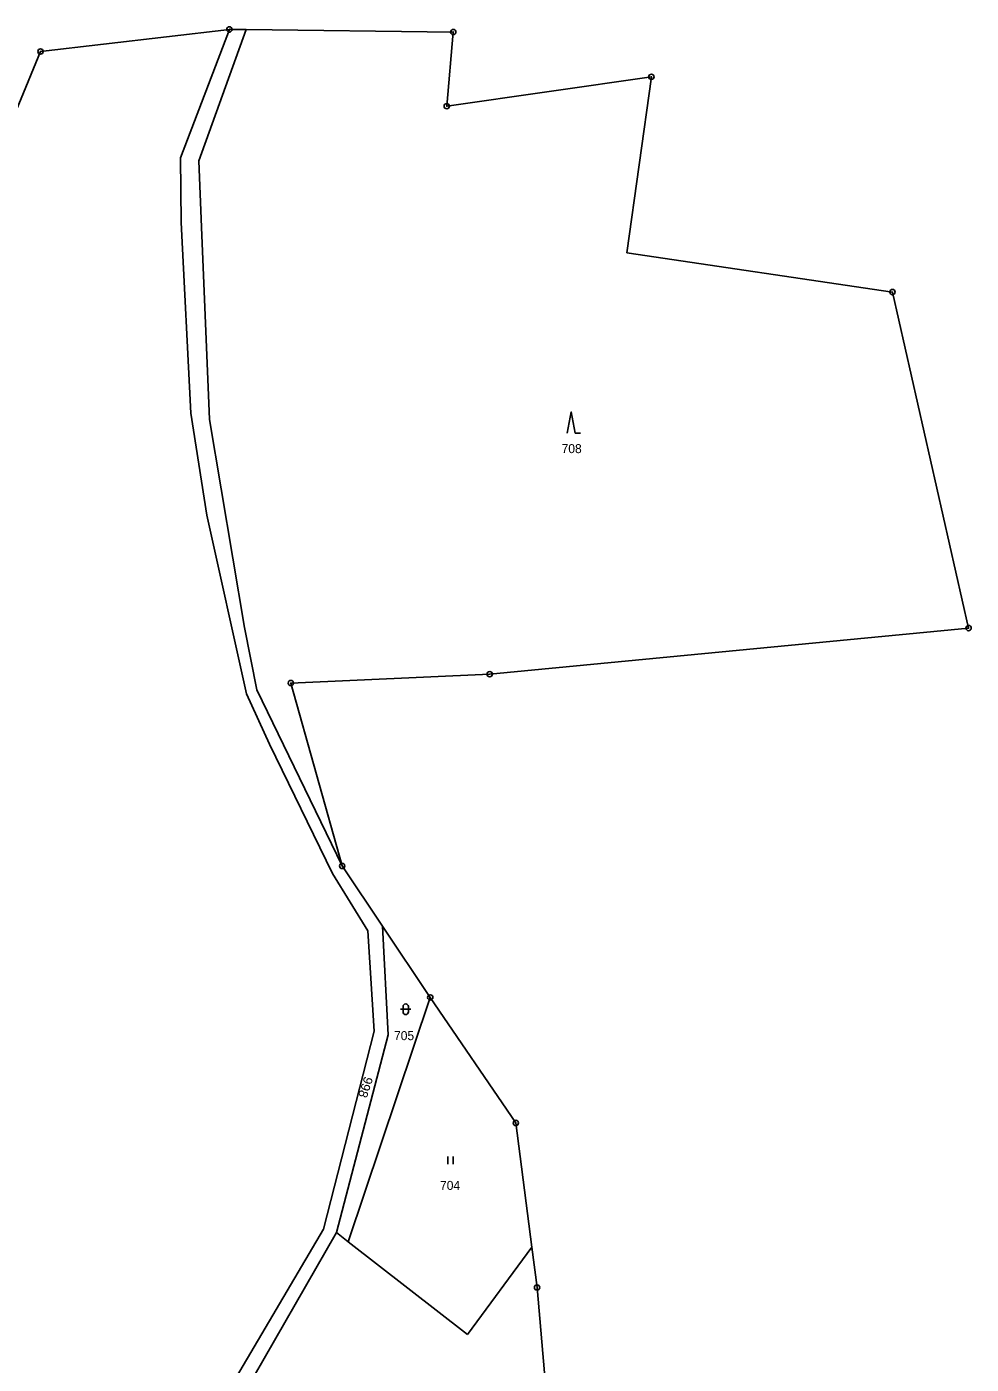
# Model space of a CAD drawing. Extents: x -744132 to -742433, y -984679 to -982287.
# Drawn here: x -742711 to -742533, y -982540.5 to -982288.4 of the extents above; entities that cross this region are included whole.
import ezdxf

# ---------------------------------------------------------------- set-up
doc = ezdxf.new("R2010")
doc.units = 0
doc.header["$LTSCALE"] = 0.68
for name, color, linetype, lineweight in [('1', 7, 'Continuous', 25), ('3', 7, 'Continuous', 25), ('8', 7, 'Continuous', 25)]:
    doc.layers.add(name, color=color, linetype=linetype, lineweight=lineweight)
doc.layers.add('2', color=7, linetype='Continuous')

msp = doc.modelspace()

# ---------------------------------------------------------------- linework, layer by layer
at = {"layer": '1'}
for p, q in [((-742672.84, -982288.93), (-742708.43, -982293.09)), ((-742672.84, -982288.93), (-742682.04, -982313.16)), ((-742669.65, -982288.97), (-742678.58, -982313.69)), ((-742669.65, -982288.97), (-742672.84, -982288.93)), ((-742630.64, -982289.43), (-742669.65, -982288.97)), ((-742631.87, -982303.4), (-742630.64, -982289.43)), ((-742708.43, -982293.09), (-742718.4, -982317.06)), ((-742593.3, -982297.87), (-742631.87, -982303.4)), ((-742597.95, -982331.03), (-742593.3, -982297.87)), ((-742682.04, -982313.16), (-742681.91, -982325.32)), ((-742678.58, -982313.69), (-742678.11, -982326.18)), ((-742680.08, -982361.27), (-742681.91, -982325.32)), ((-742676.56, -982362.43), (-742678.11, -982326.18)), ((-742547.87, -982338.43), (-742597.95, -982331.03)), ((-742533.53, -982401.74), (-742547.87, -982338.43)), ((-742677.06, -982380.44), (-742680.08, -982361.27)), ((-742676.56, -982362.43), (-742669.97, -982401.65)), ((-742669.62, -982414.1), (-742677.06, -982380.44)), ((-742669.97, -982401.65), (-742667.68, -982413.36)), ((-742623.78, -982410.43), (-742533.53, -982401.74)), ((-742661.26, -982412.09), (-742623.78, -982410.43)), ((-742651.58, -982446.56), (-742667.68, -982413.36)), ((-742651.58, -982446.56), (-742661.26, -982412.09)), ((-742665.3, -982423.64), (-742669.62, -982414.1)), ((-742665.3, -982423.64), (-742653.42, -982448.01)), ((-742643.98, -982457.9), (-742651.58, -982446.56)), ((-742653.42, -982448.01), (-742646.73, -982458.81)), ((-742634.97, -982471.34), (-742643.98, -982457.9)), ((-742642.89, -982478.37), (-742643.98, -982457.9)), ((-742634.97, -982471.34), (-742650.45, -982517.39)), ((-742618.85, -982494.99), (-742634.97, -982471.34)), ((-742652.64, -982515.65), (-742642.89, -982478.37)), ((-742615.84, -982518.37), (-742618.85, -982494.99)), ((-742655.09, -982514.99), (-742672.91, -982545.27)), ((-742670.35, -982546.43), (-742652.64, -982515.65)), ((-742652.64, -982515.65), (-742650.45, -982517.39)), ((-742650.45, -982517.39), (-742627.93, -982534.87)), ((-742615.84, -982518.37), (-742627.93, -982534.87)), ((-742615.84, -982518.37), (-742614.86, -982526)), ((-742613.28, -982544.25), (-742614.86, -982526))]:
    msp.add_line(p, q, dxfattribs=at)
msp.add_lwpolyline([(-742655.09, -982514.99), (-742645.54, -982477.71), (-742646.73, -982458.81)], dxfattribs=at)
at = {"layer": '3'}
for p, q in [((-742607.66, -982365), (-742606.664, -982365)), ((-742640.611, -982473.571), (-742638.609, -982473.571)), ((-742640.111, -982473.071), (-742640.111, -982474.072)), ((-742639.109, -982474.072), (-742639.109, -982473.071)), ((-742631.681, -982502.78), (-742631.681, -982501.28)), ((-742630.68, -982502.78), (-742630.68, -982501.28))]:
    msp.add_line(p, q, dxfattribs=at)
msp.add_lwpolyline([(-742607.66, -982365), (-742608.41, -982361), (-742609.16, -982365)], dxfattribs=at)
for centre, start, end in [((-742639.61, -982473.0709), 0, 180), ((-742639.61, -982474.0709), 180, 359.98789)]:
    msp.add_arc(centre, 0.5, start, end, dxfattribs=at)
at = {"layer": '8'}
for centre, radius in [((-742672.84, -982288.9299), 0.5), ((-742672.84, -982288.9299), 0.0303), ((-742630.64, -982289.4299), 0.5), ((-742630.64, -982289.4299), 0.0303), ((-742708.43, -982293.0899), 0.5), ((-742708.43, -982293.0899), 0.0303), ((-742593.3, -982297.8699), 0.5), ((-742593.3, -982297.8699), 0.0303), ((-742631.87, -982303.3999), 0.5), ((-742631.87, -982303.3999), 0.0303), ((-742547.87, -982338.4299), 0.5), ((-742547.87, -982338.4299), 0.0303), ((-742533.53, -982401.7399), 0.5), ((-742533.53, -982401.7399), 0.0303), ((-742623.78, -982410.4299), 0.5), ((-742623.78, -982410.4299), 0.0303), ((-742661.26, -982412.0899), 0.5), ((-742661.26, -982412.0899), 0.0303), ((-742651.58, -982446.5599), 0.5), ((-742651.58, -982446.5599), 0.0303), ((-742634.97, -982471.3399), 0.5), ((-742634.97, -982471.3399), 0.0303), ((-742618.85, -982494.9899), 0.5), ((-742618.85, -982494.9899), 0.0303), ((-742614.86, -982525.9999), 0.5), ((-742614.86, -982525.9999), 0.0303)]:
    msp.add_circle(centre, radius, dxfattribs=at)

# ---------------------------------------------------------------- texts
at = {"layer": '2'}
for s, p in [('708', (-742610.23, -982368.775)), ('705', (-742641.81, -982479.385)), ('704', (-742633.14, -982507.605))]:
    msp.add_text(s, height=1.7, dxfattribs=at).set_placement(p)
at = {"layer": '2', "width": 1.05}
msp.add_text('998', height=1.7, rotation=252, dxfattribs=at).set_placement((-742647.364, -982486.108))

doc.saveas('drawing.dxf')
